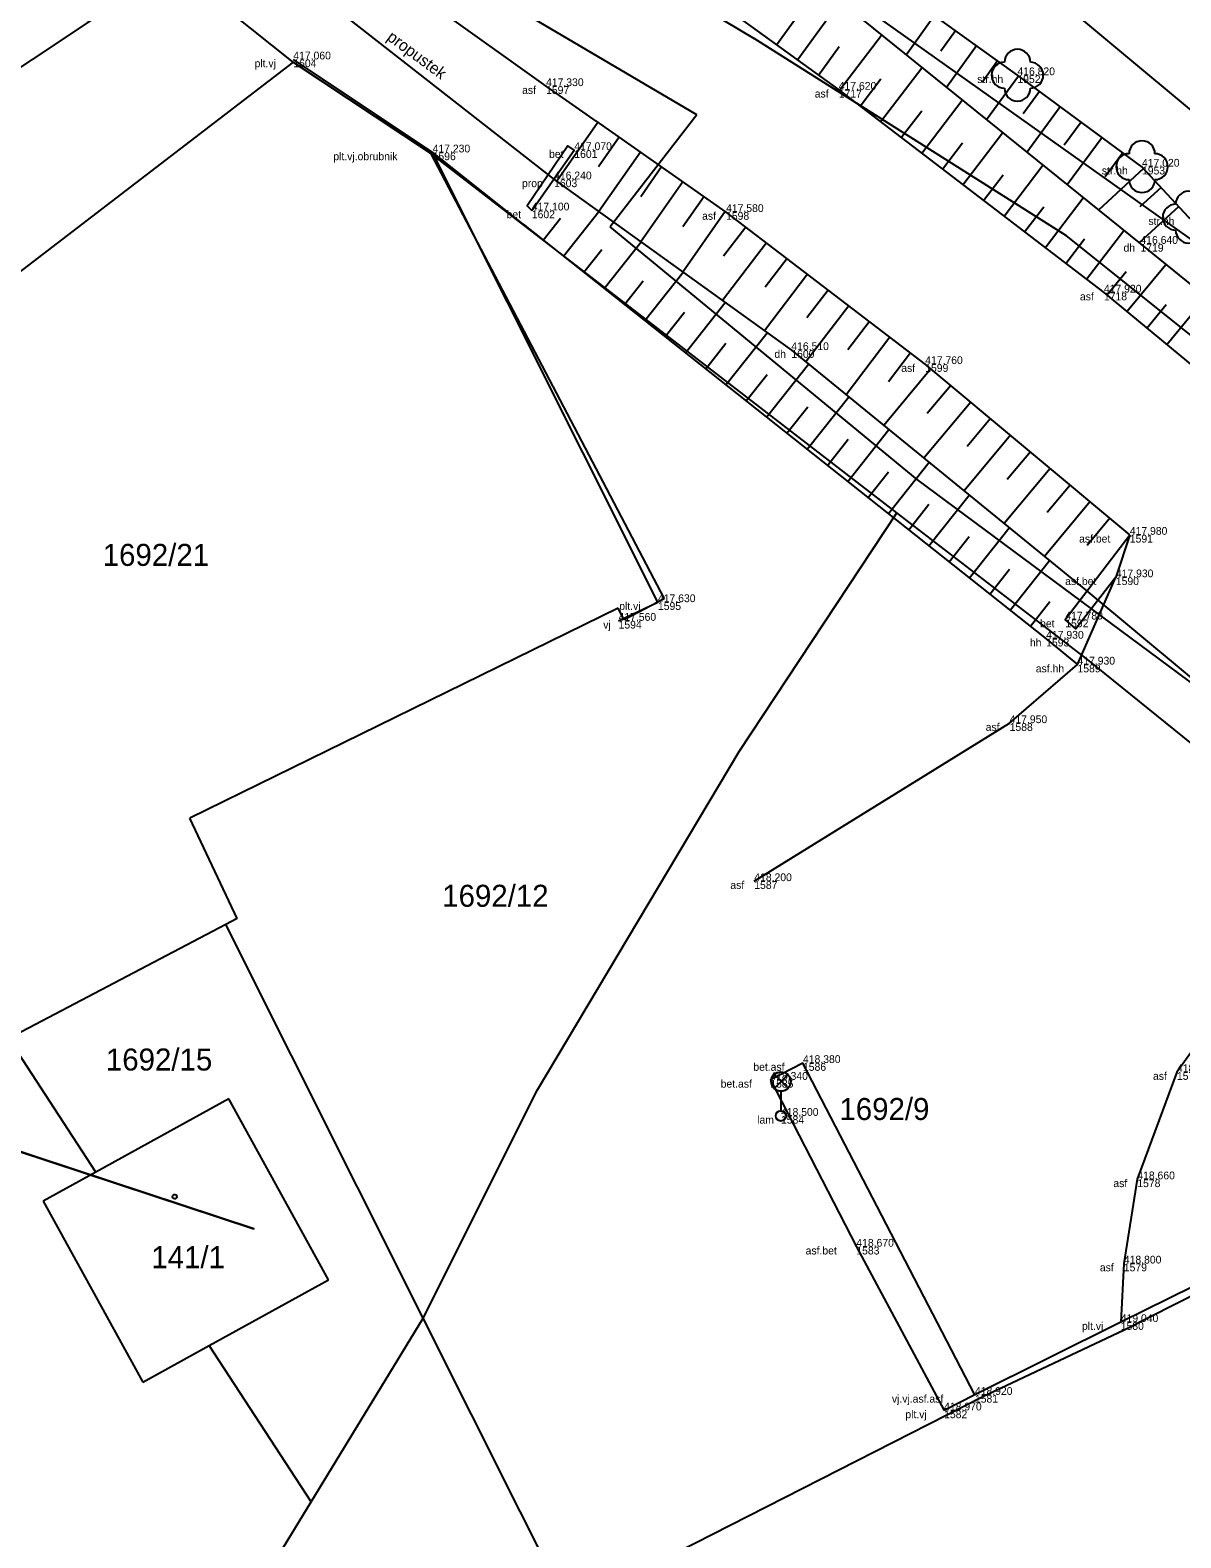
# Model space of a CAD drawing. Extents: x -747792 to -745414, y -1093712 to -1091463.
# Drawn here: x -746796.8 to -746752.3, y -1092442.7 to -1092384.5 of the extents above; entities that cross this region are included whole.
import ezdxf

# ---------------------------------------------------------------- set-up
doc = ezdxf.new("R2010")
doc.units = 0
for name, color, linetype in [('Hladina', 7, 'Continuous'), ('Koleje_dopravní prvky', 7, 'Continuous'), ('Nezařazené objekty', 7, 'Continuous'), ('Nivelační značky_hrany', 7, 'Continuous'), ('Názvy obcí_ulic', 7, 'Continuous'), ('Ploty_opěrné zdi', 7, 'Continuous'), ('Pracovní_bod JDTM STC_VC - výška', 7, 'Continuous'), ('Pracovní_bod PPBP', 7, 'Continuous'), ('Pracovní_bod PPBP - výška', 7, 'Continuous'), ('Pracovní_bod ZPBP', 7, 'Continuous'), ('Pracovní_bod ZPBP - číslo', 7, 'Continuous'), ('Rozhraní ploch', 7, 'Continuous'), ('Stromy_porost', 7, 'Continuous'), ('Výškopis', 7, 'Continuous'), ('Značky IS', 7, 'Continuous')]:
    doc.layers.add(name, color=color, linetype=linetype)

msp = doc.modelspace()

# ---------------------------------------------------------------- linework, layer by layer
at = {"layer": 'Hladina'}
for p, q in [((-746786.6, -1092385.62), (-746786.6, -1092385.62)), ((-746758.64, -1092386.23), (-746758.64, -1092386.23)), ((-746776.84, -1092386.65), (-746776.84, -1092386.65)), ((-746765.54, -1092386.79), (-746765.54, -1092386.79)), ((-746781.22, -1092389.21), (-746781.22, -1092389.21)), ((-746775.75, -1092389.12), (-746775.75, -1092389.12)), ((-746753.83, -1092389.76), (-746753.83, -1092389.76)), ((-746776.53, -1092390.25), (-746776.53, -1092390.25)), ((-746777.39, -1092391.45), (-746777.39, -1092391.45)), ((-746769.89, -1092391.51), (-746769.89, -1092391.51)), ((-746753.89, -1092392.74), (-746753.89, -1092392.74)), ((-746755.3, -1092394.62), (-746755.3, -1092394.62)), ((-746767.37, -1092396.84), (-746767.37, -1092396.84)), ((-746762.2, -1092397.38), (-746762.2, -1092397.38)), ((-746754.3, -1092403.97), (-746754.3, -1092403.97)), ((-746754.84, -1092405.61), (-746754.84, -1092405.61)), ((-746772.52, -1092406.57), (-746772.52, -1092406.57)), ((-746774.04, -1092407.29), (-746774.04, -1092407.29)), ((-746756.79, -1092407.24), (-746756.79, -1092407.24)), ((-746757.53, -1092407.98), (-746757.53, -1092407.98)), ((-746756.32, -1092408.98), (-746756.32, -1092408.98)), ((-746758.94, -1092411.24), (-746758.94, -1092411.24)), ((-746768.8, -1092417.34), (-746768.8, -1092417.34)), ((-746766.92, -1092424.36), (-746766.92, -1092424.36)), ((-746752.48, -1092424.71), (-746752.48, -1092424.71)), ((-746768.18, -1092425.01), (-746768.18, -1092425.01)), ((-746767.77, -1092426.4), (-746767.77, -1092426.4)), ((-746754.01, -1092428.85), (-746754.01, -1092428.85)), ((-746764.86, -1092431.45), (-746764.86, -1092431.45)), ((-746754.53, -1092432.1), (-746754.53, -1092432.1)), ((-746754.65, -1092434.36), (-746754.65, -1092434.36)), ((-746760.28, -1092437.17), (-746760.28, -1092437.17)), ((-746761.47, -1092437.77), (-746761.47, -1092437.77))]:
    msp.add_line(p, q, dxfattribs=at)
at = {"layer": 'Nezařazené objekty'}
for points in [[(-746772.52, -1092406.57), (-746781.22, -1092389.21)], [(-746689.71, -1092511.48), (-746691.52, -1092507.42), (-746698.75, -1092492.3), (-746705.08, -1092480.78), (-746714.94, -1092465.39), (-746724.32, -1092450.72), (-746730.02, -1092441.79), (-746735.89, -1092432.77), (-746739.69, -1092426.99), (-746754.65, -1092434.36)]]:
    msp.add_lwpolyline(points, dxfattribs=at)
at = {"layer": 'Nivelační značky_hrany'}
for points in [[(-746808.227, -1092357.17), (-746797.53, -1092364.29), (-746787.69, -1092371.13), (-746776.62, -1092378.78), (-746765.54, -1092386.79), (-746755.3, -1092394.62), (-746745.57, -1092402.66), (-746737.91, -1092409.79), (-746728.85, -1092419.26), (-746722.7, -1092426.86), (-746714.67, -1092437.95), (-746707.62, -1092449.35), (-746700.44, -1092461.3), (-746693.84, -1092472.82), (-746684.01, -1092490.2), (-746680.08, -1092497.02)], [(-746774.902, -1092388.005), (-746776.84, -1092386.65), (-746785.57, -1092380.41), (-746796.49, -1092372.78), (-746811.92, -1092362.41), (-746816.377, -1092359.347)], [(-746754.3, -1092403.97), (-746762.2, -1092397.38), (-746769.89, -1092391.51), (-746774.898, -1092388.008)], [(-746781.22, -1092389.21), (-746777.733, -1092391.973)], [(-746777.39, -1092391.45), (-746775.75, -1092389.12), (-746775.998, -1092388.951), (-746777.569, -1092391.269), (-746777.39, -1092391.45)], [(-746777.731, -1092391.974), (-746757.53, -1092407.98)], [(-746754.84, -1092405.61), (-746756.38, -1092407.6), (-746756.79, -1092407.24), (-746754.3, -1092403.97)], [(-746754.3, -1092403.97), (-746754.84, -1092405.61)], [(-746768.8, -1092417.34), (-746758.94, -1092411.24), (-746756.32, -1092408.98), (-746754.84, -1092405.61)], [(-746757.53, -1092407.98), (-746756.32, -1092408.98)], [(-746742.72, -1092416.47), (-746747.04, -1092418.66), (-746749.67, -1092420.8), (-746752.48, -1092424.71), (-746754.01, -1092428.85), (-746754.53, -1092432.1), (-746754.65, -1092434.36)], [(-746760.28, -1092437.17), (-746766.92, -1092424.36), (-746768.18, -1092425.01), (-746764.86, -1092431.45)], [(-746764.86, -1092431.45), (-746761.47, -1092437.77)]]:
    msp.add_lwpolyline(points, dxfattribs=at)
at = {"layer": 'Názvy obcí_ulic'}
for p, q in [((-746768.034, -1092425.338), (-746767.506, -1092424.81)), ((-746767.498, -1092425.335), (-746768.026, -1092424.806)), ((-746767.77, -1092425.45), (-746767.77, -1092426.2))]:
    msp.add_line(p, q, dxfattribs=at)
for centre, radius in [((-746767.77, -1092425.075), 0.375), ((-746767.77, -1092426.4), 0.2)]:
    msp.add_circle(centre, radius, dxfattribs=at)
at = {"layer": 'Ploty_opěrné zdi'}
msp.add_lwpolyline([(-746791.18, -1092429.435), (-746791.13, -1092429.445), (-746791.105, -1092429.49), (-746791.095, -1092429.52), (-746791.105, -1092429.565), (-746791.145, -1092429.6), (-746791.18, -1092429.605), (-746791.225, -1092429.59), (-746791.255, -1092429.56), (-746791.265, -1092429.52), (-746791.255, -1092429.475), (-746791.215, -1092429.44)], close=True, dxfattribs=at)
at = {"layer": 'Pracovní_bod JDTM STC_VC - výška'}
msp.add_lwpolyline([(-746666.48, -1092509.53), (-746671.18, -1092501.38), (-746679.28, -1092488.1), (-746683.01, -1092480.66), (-746691.02, -1092465.89), (-746695.91, -1092457.38), (-746697.67, -1092451.5), (-746700.29, -1092444.13), (-746704.56, -1092439.88), (-746720.11, -1092421.5), (-746727.2, -1092412.89), (-746738.25, -1092401.15), (-746749.37, -1092389.72), (-746764.79, -1092376.86), (-746776.64, -1092368.43), (-746787.43, -1092361.47), (-746799.53, -1092355.13), (-746817.34, -1092343.1), (-746824.75, -1092337.86), (-746838.2, -1092329.38), (-746851.64, -1092319.28)], dxfattribs=at)
for centre in [(-746758.64, -1092386.23), (-746753.83, -1092389.76)]:
    msp.add_circle(centre, 0.0005, dxfattribs=at)
for centre, start, end in [((-746758.64, -1092385.73), 0, 179.99999), ((-746759.14, -1092386.23), 89.99999, 269.99999), ((-746758.14, -1092386.23), 270, 89.99999), ((-746758.64, -1092386.73), 179.99999, 359.99999), ((-746754.33, -1092389.76), 89.99999, 269.99999), ((-746753.83, -1092389.26), 0, 179.99999), ((-746753.33, -1092389.76), 270, 89.99999), ((-746753.83, -1092390.26), 179.99999, 359.99999), ((-746752.03, -1092391.21), 0, 179.99999), ((-746752.53, -1092391.71), 89.99999, 269.99999), ((-746752.03, -1092392.21), 179.99999, 359.99999)]:
    msp.add_arc(centre, 0.5, start, end, dxfattribs=at)
at = {"layer": 'Pracovní_bod PPBP'}
for points in [[(-746676.31, -1092494.93), (-746679.28, -1092488.1), (-746684.61, -1092481.19), (-746692.58, -1092466.75), (-746703.9, -1092446.01), (-746716.46, -1092426.76), (-746727.325, -1092413.107), (-746739.95, -1092401.9), (-746747.98, -1092394.64), (-746752.03, -1092391.71), (-746753.83, -1092389.76), (-746758.64, -1092386.23), (-746765.82, -1092381.07), (-746787.5, -1092365.52), (-746806.41, -1092354.03)], [(-746807.12, -1092355.24), (-746796.58, -1092362.79), (-746786.63, -1092368.73), (-746775.02, -1092376.93), (-746764.6, -1092384.11), (-746753.89, -1092392.74), (-746744.6, -1092400.27), (-746734.99, -1092408.91), (-746726.93, -1092417.05), (-746720.19, -1092425.45), (-746712.76, -1092435.88), (-746705, -1092448.32), (-746698.55, -1092460.04), (-746691.76, -1092472.37), (-746682.53, -1092488.74), (-746678.42, -1092495.91)], [(-746767.13, -1092385.64), (-746765.551, -1092383.455)], [(-746767.941, -1092385.054), (-746767.158, -1092383.971)], [(-746761.843, -1092383.928), (-746762.937, -1092385.45)], [(-746761.031, -1092384.512), (-746761.594, -1092385.295)], [(-746766.32, -1092386.226), (-746765.524, -1092385.124)], [(-746765.51, -1092386.813), (-746763.884, -1092384.687)], [(-746760.219, -1092385.095), (-746761.377, -1092386.707)], [(-746759.407, -1092385.679), (-746760.002, -1092386.507)], [(-746764.716, -1092387.42), (-746763.911, -1092386.367)], [(-746763.921, -1092388.028), (-746762.327, -1092385.942)], [(-746758.595, -1092386.263), (-746759.834, -1092387.951)], [(-746757.789, -1092386.855), (-746758.422, -1092387.717)], [(-746762.333, -1092389.242), (-746760.769, -1092387.197)], [(-746756.983, -1092387.446), (-746758.275, -1092389.207)], [(-746774.838, -1092388.05), (-746776.428, -1092390.323)], [(-746763.127, -1092388.635), (-746762.337, -1092387.602)], [(-746756.177, -1092388.038), (-746756.836, -1092388.936)], [(-746774.019, -1092388.623), (-746774.817, -1092389.765)], [(-746760.744, -1092390.457), (-746759.211, -1092388.452)], [(-746755.37, -1092388.63), (-746756.716, -1092390.463)], [(-746773.199, -1092389.196), (-746774.804, -1092391.492)], [(-746761.538, -1092389.85), (-746760.764, -1092388.837)], [(-746754.564, -1092389.221), (-746755.25, -1092390.156)], [(-746772.38, -1092389.769), (-746773.186, -1092390.922)], [(-746759.155, -1092391.672), (-746757.653, -1092389.708)], [(-746753.769, -1092389.826), (-746755.511, -1092391.434)], [(-746776.53, -1092390.25), (-746767.37, -1092396.84), (-746755.999, -1092406.108)], [(-746771.56, -1092390.342), (-746773.181, -1092392.66)], [(-746759.95, -1092391.065), (-746759.191, -1092390.072)], [(-746770.741, -1092390.915), (-746771.555, -1092392.079)], [(-746757.566, -1092392.887), (-746756.095, -1092390.963)], [(-746753.091, -1092390.56), (-746753.908, -1092391.314)], [(-746776.164, -1092393.216), (-746774.8, -1092391.495)], [(-746769.921, -1092391.488), (-746771.557, -1092393.828)], [(-746758.361, -1092392.28), (-746757.618, -1092391.307)], [(-746752.413, -1092391.295), (-746753.937, -1092392.702)], [(-746776.948, -1092392.595), (-746776.28, -1092391.753)], [(-746769.125, -1092392.094), (-746769.983, -1092393.218)], [(-746755.978, -1092394.102), (-746754.537, -1092392.218)], [(-746774.596, -1092394.458), (-746773.175, -1092392.664)], [(-746768.33, -1092392.701), (-746770.03, -1092394.927)], [(-746756.772, -1092393.494), (-746756.044, -1092392.543)], [(-746775.38, -1092393.837), (-746774.684, -1092392.958)], [(-746767.535, -1092393.307), (-746768.376, -1092394.409)], [(-746773.029, -1092395.7), (-746771.549, -1092393.833)], [(-746766.741, -1092393.914), (-746768.405, -1092396.095)], [(-746755.187, -1092394.714), (-746754.438, -1092393.808)], [(-746754.416, -1092395.351), (-746752.913, -1092393.532)], [(-746773.812, -1092395.079), (-746773.087, -1092394.164)], [(-746765.946, -1092394.521), (-746766.77, -1092395.6)], [(-746771.461, -1092396.942), (-746769.924, -1092395.002)], [(-746765.151, -1092395.128), (-746766.808, -1092397.298)], [(-746753.645, -1092395.988), (-746752.891, -1092395.075)], [(-746752.874, -1092396.625), (-746751.359, -1092394.791)], [(-746772.245, -1092396.321), (-746771.491, -1092395.37)], [(-746769.893, -1092398.184), (-746768.299, -1092396.172)], [(-746764.356, -1092395.734), (-746765.194, -1092396.832)], [(-746770.677, -1092397.563), (-746769.894, -1092396.575)], [(-746763.561, -1092396.341), (-746765.257, -1092398.562)], [(-746768.326, -1092399.426), (-746766.706, -1092397.381)], [(-746762.766, -1092396.948), (-746763.624, -1092398.071)], [(-746769.11, -1092398.805), (-746768.298, -1092397.781)], [(-746761.979, -1092397.564), (-746763.801, -1092399.749)], [(-746761.211, -1092398.205), (-746762.119, -1092399.293)], [(-746767.542, -1092400.047), (-746766.736, -1092399.03)], [(-746766.758, -1092400.668), (-746765.155, -1092398.645)], [(-746760.443, -1092398.845), (-746762.251, -1092401.012)], [(-746759.675, -1092399.486), (-746760.575, -1092400.565)], [(-746765.974, -1092401.289), (-746765.177, -1092400.283)], [(-746765.191, -1092401.91), (-746763.605, -1092399.909)], [(-746758.907, -1092400.127), (-746760.7, -1092402.276)], [(-746758.14, -1092400.767), (-746759.032, -1092401.837)], [(-746763.623, -1092403.152), (-746762.054, -1092401.172)], [(-746757.372, -1092401.408), (-746759.15, -1092403.54)], [(-746764.407, -1092402.531), (-746763.618, -1092401.536)], [(-746756.604, -1092402.048), (-746757.489, -1092403.11)], [(-746762.055, -1092404.394), (-746760.504, -1092402.436)], [(-746755.836, -1092402.689), (-746757.6, -1092404.803)], [(-746762.839, -1092403.773), (-746762.059, -1092402.789)], [(-746760.488, -1092405.636), (-746758.953, -1092403.7)], [(-746755.068, -1092403.329), (-746755.946, -1092404.382)], [(-746761.272, -1092405.015), (-746760.5, -1092404.042)], [(-746758.92, -1092406.878), (-746757.403, -1092404.963)], [(-746759.704, -1092406.257), (-746758.941, -1092405.295)], [(-746758.136, -1092407.499), (-746757.382, -1092406.547)]]:
    msp.add_lwpolyline(points, dxfattribs=at)
at = {"layer": 'Pracovní_bod PPBP - výška'}
for points in [[(-746786.6, -1092385.62), (-746781.22, -1092389.21)], [(-746774.04, -1092407.29), (-746772.52, -1092406.57)], [(-746754.65, -1092434.36), (-746760.28, -1092437.17), (-746761.47, -1092437.77)]]:
    msp.add_lwpolyline(points, dxfattribs=at)
at = {"layer": 'Pracovní_bod ZPBP'}
for points in [[(-746786.72, -1092382.28), (-746776.53, -1092390.25)], [(-746756, -1092406.11), (-746742.5, -1092417.34)]]:
    msp.add_lwpolyline(points, dxfattribs=at)
at = {"layer": 'Stromy_porost'}
for points in [[(-746799.83, -1092358.59), (-746741.55, -1092399.95)], [(-746807.2, -1092361.95), (-746768.8, -1092384.81)], [(-746771.02, -1092387.76), (-746807.73, -1092366.15)], [(-746786.6, -1092385.72), (-746800.69, -1092374.51)], [(-746756.74, -1092392.43), (-746768.8, -1092384.81)], [(-746786.6, -1092385.72), (-746810.15, -1092403.77)], [(-746786.6, -1092385.72), (-746781.3, -1092389.24)], [(-746771.02, -1092387.76), (-746774.37, -1092392.08)], [(-746763.29, -1092403.12), (-746781.3, -1092389.24)], [(-746781.3, -1092389.24), (-746772.28, -1092406.44)], [(-746762.51, -1092401.83), (-746774.37, -1092392.08)], [(-746744.79, -1092401.99), (-746756.74, -1092392.43)], [(-746743.8, -1092415.7), (-746762.51, -1092401.83)], [(-746769.39, -1092412.33), (-746763.29, -1092403.12)], [(-746755.93, -1092408.79), (-746763.29, -1092403.12)], [(-746772.28, -1092406.44), (-746773.83, -1092407.25)], [(-746774.06, -1092406.8), (-746790.59, -1092414.91)], [(-746773.83, -1092407.25), (-746774.06, -1092406.8)], [(-746748.17, -1092415.05), (-746755.93, -1092408.79)], [(-746777.17, -1092425.39), (-746769.39, -1092412.33)], [(-746788.77, -1092418.78), (-746790.59, -1092414.91)], [(-746788.77, -1092418.78), (-746789.21, -1092419.01)], [(-746789.21, -1092419.01), (-746797.58, -1092423.41)], [(-746781.59, -1092434.21), (-746789.21, -1092419.01)], [(-746794.22, -1092428.57), (-746797.58, -1092423.41)], [(-746781.59, -1092434.21), (-746777.17, -1092425.39)], [(-746789.09, -1092425.74), (-746794.22, -1092428.57)], [(-746785.24, -1092432.73), (-746789.09, -1092425.74)], [(-746739.55, -1092427.1), (-746754.52, -1092434.67)], [(-746794.22, -1092428.57), (-746796.26, -1092429.69)], [(-746796.26, -1092429.69), (-746792.41, -1092436.68)], [(-746789.85, -1092435.27), (-746785.24, -1092432.73)], [(-746785.91, -1092441.3), (-746781.59, -1092434.21)], [(-746775.98, -1092445.39), (-746781.59, -1092434.21)], [(-746754.52, -1092434.67), (-746759.97, -1092437.25)], [(-746792.41, -1092436.68), (-746789.85, -1092435.27)], [(-746785.91, -1092441.3), (-746789.85, -1092435.27)], [(-746759.97, -1092437.25), (-746775.98, -1092445.39)], [(-746793.79, -1092454.2), (-746785.91, -1092441.3)]]:
    msp.add_lwpolyline(points, dxfattribs=at)
at = {"layer": 'Značky IS'}
for points in [[(-746811.08, -1092395.19), (-746775.12, -1092371.27), (-746794.557, -1092384.199)], [(-746837.903, -1092414.342), (-746788.13, -1092430.76), (-746814.678, -1092422.003)]]:
    msp.add_lwpolyline(points, dxfattribs=at)

# ---------------------------------------------------------------- texts
at = {"layer": 'Koleje_dopravní prvky'}
for s, p in [('1692/21', (-746793.961, -1092405.17)), ('1692/12', (-746780.851, -1092418.33)), ('1692/15', (-746793.838, -1092424.65)), ('1692/9', (-746765.514, -1092426.56)), ('141/1', (-746792.085, -1092432.28))]:
    msp.add_text(s, height=0.85, dxfattribs=at).set_placement(p)
at = {"layer": 'Pracovní_bod ZPBP - číslo'}
msp.add_text('propustek', height=0.45, rotation=323.56516, dxfattribs=at).set_placement((-746783.022, -1092384.842))
at = {"layer": 'Rozhraní ploch'}
for s, p in [(' plt.vj', (-746788.208, -1092385.92)), ('1604', (-746786.6, -1092385.92)), (' str.hh', (-746760.303, -1092386.53)), ('1952', (-746758.64, -1092386.53)), (' asf', (-746777.877, -1092386.95)), ('1597', (-746776.84, -1092386.95)), (' asf', (-746766.577, -1092387.09)), ('1717', (-746765.54, -1092387.09)), (' plt.vj.obrubnik', (-746785.166, -1092389.51)), ('1596', (-746781.22, -1092389.51)), (' bet', (-746776.836, -1092389.42)), ('1601', (-746775.75, -1092389.42)), (' str.hh', (-746755.493, -1092390.06)), ('1953', (-746753.83, -1092390.06)), (' prop', (-746777.881, -1092390.55)), ('1603', (-746776.53, -1092390.55)), (' bet', (-746778.476, -1092391.75)), ('1602', (-746777.39, -1092391.75)), (' asf', (-746770.927, -1092391.81)), ('1598', (-746769.89, -1092391.81)), (' str.hh', (-746753.693, -1092392.01)), (' dh', (-746754.655, -1092393.04)), ('1719', (-746753.89, -1092393.04)), (' asf', (-746756.337, -1092394.92)), ('1718', (-746755.3, -1092394.92)), (' dh', (-746768.135, -1092397.14)), ('1600', (-746767.37, -1092397.14)), (' asf', (-746763.237, -1092397.68)), ('1599', (-746762.2, -1092397.68)), (' asf.bet', (-746756.369, -1092404.27)), ('1591', (-746754.3, -1092404.27)), (' asf.bet', (-746756.909, -1092405.91)), ('1590', (-746754.84, -1092405.91)), (' plt.vj', (-746774.128, -1092406.87)), ('1595', (-746772.52, -1092406.87)), (' vj', (-746774.744, -1092407.59)), ('1594', (-746774.04, -1092407.59)), (' bet', (-746757.876, -1092407.54)), ('1592', (-746756.79, -1092407.54)), (' hh', (-746758.269, -1092408.28)), ('1593', (-746757.53, -1092408.28)), (' asf.hh', (-746758.042, -1092409.28)), ('1589', (-746756.32, -1092409.28)), (' asf', (-746759.977, -1092411.54)), ('1588', (-746758.94, -1092411.54)), (' asf', (-746769.837, -1092417.64)), ('1587', (-746768.8, -1092417.64)), (' bet.asf', (-746768.949, -1092424.66)), ('1586', (-746766.92, -1092424.66)), (' asf', (-746753.517, -1092425.01)), ('1577', (-746752.48, -1092425.01)), (' bet.asf', (-746770.209, -1092425.31)), ('1585', (-746768.18, -1092425.31)), (' lam', (-746768.8, -1092426.7)), ('1584', (-746767.77, -1092426.7)), (' asf', (-746755.047, -1092429.15)), ('1578', (-746754.01, -1092429.15)), (' asf.bet', (-746766.929, -1092431.75)), ('1583', (-746764.86, -1092431.75)), (' asf', (-746755.567, -1092432.4)), ('1579', (-746754.53, -1092432.4)), (' plt.vj', (-746756.258, -1092434.66)), ('1580', (-746754.65, -1092434.66)), (' vj.vj.asf.asf', (-746763.598, -1092437.47)), ('1581', (-746760.28, -1092437.47)), (' plt.vj', (-746763.078, -1092438.07)), ('1582', (-746761.47, -1092438.07))]:
    msp.add_text(s, height=0.3, dxfattribs=at).set_placement(p)
at = {"layer": 'Výškopis'}
for s, p in [('417,060', (-746786.6, -1092385.62)), ('417,330', (-746776.84, -1092386.65)), ('416,820', (-746758.64, -1092386.23)), ('417,620', (-746765.54, -1092386.79)), ('417,230', (-746781.22, -1092389.21)), ('417,070', (-746775.75, -1092389.12)), ('417,020', (-746753.83, -1092389.76)), ('416,240', (-746776.53, -1092390.25)), ('417,100', (-746777.39, -1092391.45)), ('417,580', (-746769.89, -1092391.51)), ('416,640', (-746753.89, -1092392.74)), ('417,920', (-746755.3, -1092394.62)), ('416,510', (-746767.37, -1092396.84)), ('417,760', (-746762.2, -1092397.38)), ('417,980', (-746754.3, -1092403.97)), ('417,930', (-746754.84, -1092405.61)), ('417,630', (-746772.52, -1092406.57)), ('417,560', (-746774.04, -1092407.29)), ('417,780', (-746756.79, -1092407.24)), ('417,930', (-746757.53, -1092407.98)), ('417,930', (-746756.32, -1092408.98)), ('417,950', (-746758.94, -1092411.24)), ('418,200', (-746768.8, -1092417.34)), ('418,380', (-746766.92, -1092424.36)), ('418,340', (-746768.18, -1092425.01)), ('418,490', (-746752.48, -1092424.71)), ('418,500', (-746767.77, -1092426.4)), ('418,660', (-746754.01, -1092428.85)), ('418,670', (-746764.86, -1092431.45)), ('418,800', (-746754.53, -1092432.1)), ('419,040', (-746754.65, -1092434.36)), ('418,920', (-746760.28, -1092437.17)), ('418,970', (-746761.47, -1092437.77))]:
    msp.add_text(s, height=0.3, dxfattribs=at).set_placement(p)

doc.saveas('drawing.dxf')
